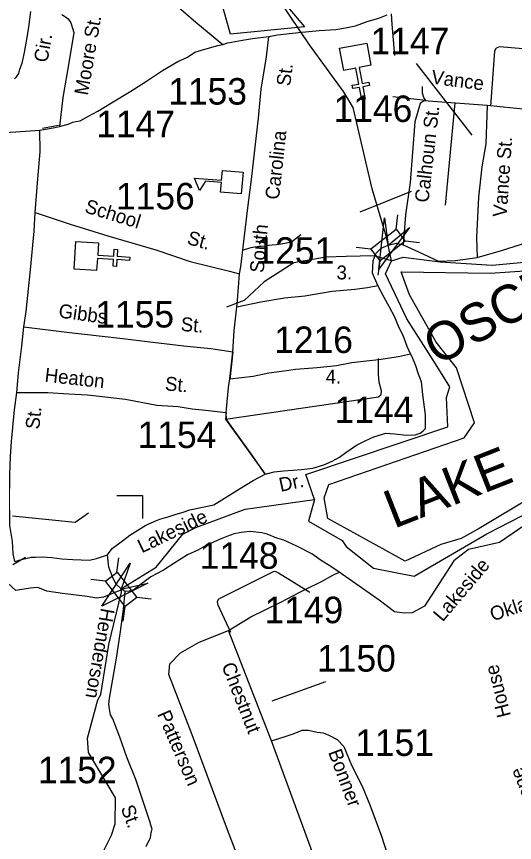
# Model space of a CAD drawing. Extents: x 884530 to 1028605, y 526725 to 653634.
# Drawn here: x 960824 to 963175, y 578430 to 582326 of the extents above; entities that cross this region are included whole.
import ezdxf

# ---------------------------------------------------------------- set-up
doc = ezdxf.new("R2010")
doc.units = 0
for name, color, linetype in [('Exist Boundary Political City Limit New', 7, 'Continuous'), ('Exist Cultural Church CELL', 7, 'Continuous'), ('Exist Cultural Educational Facility Elementary CELL', 7, 'Continuous'), ('Exist Hydrographic Bay Label', 7, 'Continuous'), ('Exist Hydrographic Buffer Line', 7, 'Continuous'), ('Exist Hydrographic Creek Single Shore', 7, 'Continuous'), ('Exist Hydrographic Lake Shore Label', 7, 'Continuous'), ('Exist Hydrographic Lock CELL', 7, 'Continuous'), ('Exist Road Non-System Type 51', 7, 'Continuous'), ('Exist Road Non-System Type 51 Label', 7, 'Continuous'), ('Exist Road Secondary Structure Standard Bridge Attributed CELL', 7, 'Continuous'), ('Exist Road Secondary Structure Standard Bridge CELL', 7, 'Continuous'), ('Exist Road Secondary Type 41 Attributed', 7, 'Continuous'), ('Exist Road Secondary Type 51 Attributed', 7, 'Continuous'), ('Exist Road Secondary Type 51 Label', 7, 'Continuous'), ('Exist Road Secondary Type 51 Number Label', 7, 'Continuous'), ('Map Preparation Boundary City Limit Buffer Line', 7, 'Continuous')]:
    doc.layers.add(name, color=color, linetype=linetype)

msp = doc.modelspace()

# ---------------------------------------------------------------- linework, layer by layer
at = {"layer": 'Exist Boundary Political City Limit New'}
msp.add_lwpolyline([(962419.1, 584388.8), (962396.4, 584268.4), (962220.6, 582634.1), (962071.3, 582412.4), (962183.8, 582276.6), (961834.8, 582241.7), (961673.8, 582812.8), (961548.6, 582823.6), (961361.7, 582493.9), (961067, 582544.3), (961105.4, 583066.7), (958842.8, 583349.2)], dxfattribs=at)
at = {"layer": 'Exist Cultural Church CELL'}
for points in [[(962497.7, 582095.6), (962441.8, 582085), (962455.9, 582010.1), (962487.3, 582016), (962490.2, 582000.3), (962458.8, 581994.4), (962469.9, 581935.3), (962454.1, 581932.4), (962443, 581991.5), (962411.6, 581985.6), (962408.6, 582001.3), (962440.1, 582007.2), (962426.1, 582082), (962369.4, 582071.5), (962349.7, 582176.1), (962478.1, 582200.2)], [(961211.1, 581257.6), (961207.6, 581200.8), (961283.6, 581195.9), (961285.7, 581227.8), (961301.6, 581226.8), (961299.6, 581194.9), (961359.6, 581191), (961358.5, 581175.1), (961298.5, 581178.9), (961296.5, 581147), (961280.5, 581148), (961282.6, 581179.9), (961206.6, 581184.8), (961202.8, 581127.3), (961096.6, 581134), (961104.9, 581264.4)]]:
    msp.add_lwpolyline(points, close=True, dxfattribs=at)
at = {"layer": 'Exist Cultural Educational Facility Elementary CELL'}
msp.add_lwpolyline([(961885.4, 581489.5), (961787.8, 581497.7), (961791.6, 581543.5), (961716.8, 581549.8), (961688.8, 581504.9), (961664.4, 581563.8), (961792.4, 581553.1), (961796.3, 581599), (961893.8, 581590.8)], close=True, dxfattribs=at)
at = {"layer": 'Exist Hydrographic Bay Label'}
for points in [[(962231.2, 580047.9), (962203.2, 579944.6), (962362.3, 579854.1), (962381, 579826), (962508.9, 579723), (962702.2, 579685.5), (963045.3, 579885.3), (963322.8, 580028.9), (963350.9, 580088.2), (963372.7, 580225.5), (963291.6, 580509.5), (963332.2, 580678.1), (963428.9, 580809.2), (963717.4, 581064.9), (963844.4, 581118.1), (963890.4, 581296.1), (963856.1, 581392.8)], [(962231.2, 580047.9), (962190.7, 580166.2), (962861.3, 580390.9), (962855, 580528.3), (962870.6, 580578.2), (962802, 580687.4), (962666.4, 580899.5), (962566.6, 581111.7), (962595.4, 581173), (962650.1, 581191.3), (962823.8, 581168.1)]]:
    msp.add_lwpolyline(points, dxfattribs=at)
at = {"layer": 'Exist Hydrographic Buffer Line'}
msp.add_lwpolyline([(963263.6, 580063.2), (963007.8, 579910.2), (962923.6, 579863.4), (962827, 579835.3), (962658.6, 579757.3), (962293.7, 579957.1), (962276.6, 580055.6), (962299.2, 580117.5), (962937.2, 580338), (962985.7, 580409.9), (962901.8, 580668.7), (962805.1, 580790.4), (962680.3, 581012.9), (962639.7, 581122.1), (963060.7, 581114.5), (963224.2, 581126.9)], dxfattribs=at)
at = {"layer": 'Exist Hydrographic Creek Single Shore'}
for points in [[(962595.4, 581173), (962571.5, 581284.8), (962503.2, 581512.8), (962414.3, 581897.2), (962368.7, 581972.4), (962207.5, 582192.9), (961744.5, 582879.2), (961617, 582987.1), (961505.9, 583064.7), (961336.7, 583108.1), (960713.9, 583186.3), (960566.8, 583274.5), (960148.7, 583287.6), (959704.9, 583646.6), (959288.3, 583677.7), (959032.2, 583745.2), (958893.2, 583826.8), (958593.5, 584078.9), (958148.8, 584242.1), (957369.3, 584369.4), (957205.1, 584441.6)], [(961320.5, 579627.6), (961311.7, 579618.6), (961235.3, 579586.3), (961201.6, 579581.8), (961157.8, 579589.6), (961042.1, 579604.3), (960967.9, 579615.5), (960925.2, 579632.4), (960888.2, 579629), (960821.3, 579618.6), (960598.8, 579821), (960504.4, 579915.4), (960482.1, 580094.7), (960172.1, 580740.4), (960009.5, 581126.8), (959664, 581416.7), (959491.2, 581482.7), (959310.4, 581426), (958932.1, 581217.6)], [(962595.4, 581173), (962513, 581196.1), (962380.1, 581193.6), (962284.4, 581191.3), (962134, 581163.9), (961992.8, 581075), (961899.3, 580986.1), (961815, 580954.1)], [(961320.5, 579627.6), (961484.5, 579728.3), (961609.5, 579884), (961670.2, 579915.4), (961904.4, 580002), (962231.2, 580047.9)], [(961152.8, 578225.7), (961272.9, 578464.9), (961289.8, 578518), (961291.4, 578639.5), (961164, 578853.7), (961159.5, 578921.2), (961208.9, 579102.2), (961222.4, 579126.9), (961260.6, 579364.1), (961320.4, 579611.1), (961320.5, 579627.6)]]:
    msp.add_lwpolyline(points, dxfattribs=at)
at = {"layer": 'Exist Hydrographic Lock CELL'}
msp.add_lwpolyline([(962823.8, 581168.1), (963070.1, 581153.4), (963220.6, 581166.8), (963388.3, 581352.3), (963494.4, 581461.5), (963640.9, 581545.8), (963821.8, 581505.2), (963856.1, 581392.8)], dxfattribs=at)
at = {"layer": 'Exist Road Non-System Type 51'}
for p, q in [((962756.6, 581929.3), (962601.5, 581946.4)), ((962893.8, 581918.9), (962847.8, 581435.5)), ((961023.3, 581810.9), (960947, 581798)), ((961845, 580744.5), (961831.7, 580613.2)), ((961814.3, 580457.1), (961810.6, 580426.7)), ((961810.6, 580426.7), (961998.4, 580166.7))]:
    msp.add_line(p, q, dxfattribs=at)
for points in [[(962593.1, 582338.2), (962596.4, 582290.2), (962608.3, 582141.3)], [(963271.8, 582168.7), (963103.9, 582183), (963089.1, 582175.8), (963080.9, 582162), (963062.6, 581903.5)], [(962756.6, 581929.3), (962747.2, 581943.7), (962741.6, 581964.7), (962740.8, 581996)], [(961895.3, 581225.7), (961921.3, 581233.3), (961932.6, 581236.1), (961947.3, 581238.8), (961959.6, 581240.6), (961969.1, 581241.8), (961978.8, 581242.8), (961996.2, 581244.7), (962013.6, 581246.6), (962030.7, 581248.4), (962052, 581250.6), (962073.9, 581253.5), (962099.2, 581258), (962111.6, 581260.6), (962122.1, 581262.9), (962166.4, 581297.4)], [(961810.6, 580426.7), (962532.7, 580531.1), (962545.7, 580542.2), (962548.2, 580560.1), (962536.7, 580601.3), (962533.8, 580637.4), (962532.7, 580668.4), (962533.8, 580712.6)], [(960805.6, 579970.5), (961100.7, 579940.7), (961165, 579984.5)], [(962209.6, 579609.4), (962061.1, 579699.5), (962050.7, 579705.8), (962043.6, 579708.6), (962036.5, 579706.3), (961803.7, 579590.1), (961786.7, 579582.2), (961775.7, 579576.1), (961772.4, 579563.5), (961775.2, 579550.7), (961834, 579421.9)]]:
    msp.add_lwpolyline(points, dxfattribs=at)
at = {"layer": 'Exist Road Secondary Structure Standard Bridge Attributed CELL'}
for points in [[(962679.5, 581330.7), (962535, 581134.2), (962562, 581376.6), (962579.4, 581247.8)], [(961445.1, 579653.1), (961227, 579543.9), (961361.2, 579747.5), (961318.2, 579624.8)]]:
    msp.add_lwpolyline(points, close=True, dxfattribs=at)
at = {"layer": 'Exist Road Secondary Structure Standard Bridge CELL'}
for p, q in [((962616.3, 581322), (962624.7, 581390.4)), ((962658.7, 581267.6), (962727.2, 581259.2)), ((962428.5, 581237.6), (962497, 581229.2)), ((962532, 581105.1), (962540.4, 581173.6)), ((960806.7, 579741.4), (960866.4, 579775.9)), ((961298.4, 579704.2), (961306.8, 579772.6)), ((961244, 579661.7), (961175.6, 579670.1)), ((961460.9, 579577.5), (961392.4, 579585.9)), ((961328.4, 579473.9), (961336.8, 579542.4))]:
    msp.add_line(p, q, dxfattribs=at)
for points in [[(962497, 581229.2), (962616.1, 581322.2), (962659.5, 581266.6), (962540.4, 581173.6)], [(961336.8, 579542.4), (961243.8, 579661.5), (961299.4, 579704.9), (961392.4, 579585.9)]]:
    msp.add_lwpolyline(points, close=True, dxfattribs=at)
at = {"layer": 'Exist Road Secondary Type 41 Attributed'}
for points in [[(960814.2, 582032.2), (960824.6, 582042), (960835.1, 582057.6), (960839.7, 582077.5), (960850.6, 582105.1), (960862.5, 582156.7), (960874.9, 582226.2), (960882.8, 582274.8), (960891.5, 582348.7)], [(961038.8, 582334.6), (961056.4, 582323.9), (961068.1, 582314.1), (961081.3, 582295.6), (961088.4, 582270), (961095.8, 582250.6), (961073.1, 582117.4), (961043.2, 581944.4), (961026.7, 581807.6)], [(961436.3, 578410.8), (961447.1, 578434.6), (961456.9, 578452), (961460, 578477.2), (961465.5, 578492.2), (961456.9, 578516.7), (961457.1, 578519.3), (961388.2, 578726.1), (961345.7, 578831.6), (961313, 578926.9), (961279.9, 579012.2), (961268.7, 579032.4), (961263.7, 579060.7), (961260.3, 579082.8), (961263.3, 579110.7), (961278.5, 579200.2), (961295.9, 579299.7), (961313.8, 579413.2), (961329.9, 579528.7), (961337.2, 579613.4)], [(962028.1, 578909.6), (962092.4, 578928.9), (962134.9, 578943.5), (962173.7, 578959.9), (962202.8, 578959.9), (962243.4, 578950.1), (962271.4, 578947.2), (962299.5, 578936.3), (962338.9, 578914.9), (962369.9, 578883.1), (962405.7, 578794), (962455.9, 578694.6), (962492.8, 578607.7), (962547.1, 578459.8), (962584.6, 578342.2), (962634.5, 578226.3), (962651.4, 578168.5), (962707.9, 578044.6)]]:
    msp.add_lwpolyline(points, dxfattribs=at)
at = {"layer": 'Exist Road Secondary Type 51 Attributed'}
for points in [[(960315.1, 582621.7), (960408.2, 582621.7), (960459.9, 582621.7), (960524.6, 582701.9), (960633.3, 582808.1), (960744.5, 582854.7), (960850.6, 582885.8), (960910.1, 582878), (960948.9, 582836.6), (960933.4, 582660.5), (960933.4, 582582.9), (960990.3, 582541.4), (961143, 582510.4), (961305.9, 582489.7), (961448.2, 582456), (961554.3, 582399), (961670.6, 582298.5), (961798.1, 582194.4)], [(962015, 582230.7), (962056.8, 582239.1), (962156, 582251.1), (962253.5, 582259.6), (962331.4, 582265.2), (962377.8, 582271.7), (962424.6, 582281.9), (962484.5, 582304.1), (962534.1, 582317.8), (962573.4, 582333.2)], [(961798.1, 582194.4), (961822.4, 582201.5), (961890.8, 582213.4), (961939.1, 582221.8), (962015, 582230.7)], [(961877.1, 581112.4), (961882.9, 581144.5), (961897, 581264.1), (961914.8, 581410.3), (961933.6, 581557.5), (961947.9, 581681.1), (961959.3, 581778.6), (961966.1, 581847), (961979.8, 581982.3), (962004.8, 582134.8), (962015, 582230.7)], [(961026.7, 581807.6), (961068.5, 581817.7), (961089.7, 581826.8), (961104.2, 581829.8), (961124.6, 581833.9), (961161.2, 581854.2), (961207.8, 581880), (961272.5, 581918.9), (961364.4, 581973.3), (961433.9, 582017), (961513.9, 582071.3), (961585.6, 582112.9), (961632.1, 582134.6), (961666.9, 582157.5), (961712.9, 582172.3), (961774.1, 582189.8), (961798.1, 582194.4)], [(963045.5, 581906.3), (962746.7, 581928.5), (962729.4, 581916.1), (962704.7, 581829.7), (962682.5, 581543), (962660.3, 581389.8), (962650.4, 581249)], [(963045.5, 581906.3), (963040.6, 581725.9), (963020.8, 581617.2), (963006, 581473.8), (962996.1, 581283.6), (962998.6, 581189.7)], [(963292.4, 581881.6), (963045.5, 581906.3)], [(960933.8, 581790.3), (960997.5, 581801), (961026.7, 581807.6)], [(960070.3, 581765.7), (960158.2, 581772.8), (960215.1, 581775.4), (960305.6, 581775.4), (960509.8, 581766.4), (960636, 581770.5), (960821.3, 581781.9), (960933.8, 581790.3)], [(960913.3, 581401.5), (960924.8, 581559.3), (960936.1, 581686.7), (960933.8, 581790.3)], [(960859.6, 580861.2), (960869.7, 580934.8), (960890.5, 581130.3), (960908, 581313.9), (960913.3, 581401.5)], [(960913.3, 581401.5), (961078.3, 581346), (961255.1, 581290.6), (961482, 581225.4), (961644.5, 581170.6), (961829.2, 581124.4), (961877.1, 581112.4)], [(963878.3, 581401.5), (963938.3, 581285.2), (963900.9, 581203.2), (963845.3, 581104.4), (963728, 581036.5), (963542.8, 580919.1), (963413.2, 580727.6), (963252.7, 580548.4), (963314.4, 580350.8), (963400.8, 580202.5), (963376.1, 580122.2), (963283.5, 579967.8), (963104.5, 579844.2), (962958.1, 579811.5), (962888.4, 579757.7), (962751.2, 579545), (962691.8, 579512.4), (962653.8, 579510.6), (962609.4, 579518.2), (962536.6, 579572.4), (962348.1, 579704.1)], [(962998.6, 581189.7), (963114.6, 581221.8), (963208.5, 581251.4), (963290, 581295.9), (963336.9, 581342.9), (963373.9, 581399.7)], [(962579.4, 581247.9), (962616.9, 581256.2), (962650.4, 581249)], [(962530.7, 581056.9), (962505, 581114.7), (962507.5, 581173.7), (962521.4, 581208), (962545.1, 581232.8), (962579.4, 581247.9)], [(962650.4, 581249), (962741.8, 581207), (962815.8, 581172.4), (962897.3, 581174.8), (962998.6, 581189.7)], [(961865.3, 580955.7), (961868.3, 580985.6), (961877.1, 581112.4)], [(961865.3, 580955.7), (961978.5, 580979.3), (962089.3, 580999.4), (962185.3, 581008.1), (962314.2, 581029.7), (962421.6, 581039.1), (962482, 581047), (962530.7, 581056.9)], [(962684.7, 580735.1), (962669.3, 580769.3), (962649.7, 580820.3), (962631.6, 580856.6), (962608.6, 580911.2), (962585.6, 580954.2), (962559.3, 581001.1), (962530.7, 581056.9)], [(961845, 580744.5), (961852.5, 580843.1), (961865.3, 580955.7)], [(960826.2, 580552.9), (960834.5, 580645.7), (960849.1, 580770.7), (960859.6, 580861.2)], [(960859.6, 580861.2), (961074.5, 580835.9), (961146.1, 580827.7), (961327, 580806.6), (961453.2, 580791.8), (961629.1, 580771), (961741.8, 580759.7), (961845, 580744.5)], [(961831, 580616.9), (961845, 580744.5)], [(961831, 580616.9), (961942.2, 580628.9), (962016.1, 580644.8), (962098.3, 580655.9), (962141.8, 580662.1), (962244.2, 580670.4), (962335.7, 580680.3), (962408, 580693), (962476.4, 580700.8), (962534.1, 580707.7), (962628.2, 580721.4), (962684.7, 580735.1)], [(961998.4, 580166.7), (962040.5, 580178.7), (962084.4, 580182.4), (962130.1, 580185.9), (962170.5, 580188.8), (962222.8, 580195), (962274.5, 580211.3), (962314.8, 580228.5), (962349.2, 580247.7), (962378.9, 580269.8), (962429.7, 580303.3), (962470.9, 580324.4), (962511.2, 580342.6), (962567.7, 580359.9), (962608.9, 580357), (962666.4, 580350.3), (962707.1, 580352.4), (962729.4, 580360.9), (962744.8, 580371.2), (962753.3, 580381.5), (962754.5, 580386.1), (962755.5, 580403), (962755.5, 580419.3), (962755.5, 580447.1), (962742.5, 580543), (962736, 580603.2), (962722.3, 580639.2), (962709.7, 580677.3), (962692.9, 580719.9), (962684.7, 580735.1)], [(961814.3, 580457.1), (961815.8, 580473.9), (961825.3, 580576.4), (961831, 580616.9)], [(960816.3, 579754.4), (960809.1, 579793.2), (960805, 579849.3), (960793.2, 579925.6), (960792.6, 579967.6), (960790.9, 580029.7), (960793.6, 580165.7), (960795.9, 580250.9), (960800.3, 580320.8), (960814.9, 580470.4), (960826.2, 580552.9)], [(960826.2, 580552.9), (960973, 580551.8), (961070.9, 580546.4), (961158.8, 580541.2), (961338.3, 580521), (961487.3, 580492.7), (961588.3, 580485.9), (961653.3, 580475.6), (961716.6, 580468.8), (961814.3, 580457.1)], [(961998.4, 580166.7), (961940.4, 580251.6), (961882.9, 580329.9), (961815.8, 580425.6), (961814.3, 580457.1)], [(961254.3, 579787.2), (961275.9, 579816.1), (961325.5, 579852.1), (961359.8, 579879.5), (961435, 579926.7), (961485.9, 579949.1), (961501.7, 579954.8), (961545.5, 579967.2), (961572.9, 579977.4), (961610.5, 579987.7), (961643, 579998), (961755.9, 580022), (961877.6, 580098.2), (961942.3, 580137), (961998.4, 580166.7)], [(962348.1, 579704.1), (962308, 579732), (962262.7, 579759.9), (962218.3, 579791), (962147.4, 579827.5), (962086.5, 579856.4), (962052.9, 579865.5), (962008.4, 579883.7), (961982.2, 579890.7), (961928.2, 579895.9), (961884.7, 579892.4), (961851.6, 579885.4), (961816.9, 579872.7), (961794.5, 579863.5), (961757.5, 579847.1), (961713.2, 579827.9), (961680.6, 579808.9), (961631, 579786.5), (961571.6, 579748.5), (961518.3, 579714.4), (961459.2, 579682.3), (961415.1, 579649.7), (961378.3, 579621.6), (961355.9, 579614.4), (961337.2, 579613.4)], [(960816.3, 579754.4), (960853.4, 579766.5), (960868.6, 579768.5), (960893, 579775.8), (960912.2, 579775), (960948.3, 579777.7), (960991.2, 579773.6), (961038.8, 579767.8), (961090.3, 579763.7), (961168.3, 579761), (961201.4, 579768.7), (961254.3, 579787.2)], [(961317.8, 579626), (961294.6, 579648.4), (961279.6, 579678.5), (961260.4, 579727.6), (961254.3, 579787.2)], [(961824.4, 579429.8), (961931, 579494), (962071.6, 579563), (962161.2, 579610), (962189.7, 579625), (962267, 579662.3), (962318, 579690.7), (962348.1, 579704.1)], [(961337.2, 579613.4), (961317.8, 579626)], [(962144.7, 577656.5), (962053.8, 577881.1), (961820.8, 578489.6), (961653.2, 578937.8), (961544, 579222.1), (961547.6, 579273.1), (961598.6, 579324.1), (961686, 579375.1), (961824.4, 579429.8)], [(962028.1, 578909.6), (961824.4, 579429.8)], [(962416.8, 577864.1), (962232.1, 578352), (962028.1, 578909.6)]]:
    msp.add_lwpolyline(points, dxfattribs=at)
at = {"layer": 'Exist Road Secondary Type 51 Label'}
for points in [[(962446.3, 581404.7), (962688.5, 581502.6)], [(961298.2, 580065.8), (961418.9, 580065.8), (961418.9, 579958.3)], [(962283.8, 579188.1), (962029.6, 579095.9)]]:
    msp.add_lwpolyline(points, dxfattribs=at)
at = {"layer": 'Exist Road Secondary Type 51 Number Label'}
msp.add_lwpolyline([(962976, 581765.9), (962712.3, 582104.2)], dxfattribs=at)
at = {"layer": 'Map Preparation Boundary City Limit Buffer Line'}
msp.add_lwpolyline([(962419.1, 584388.8), (962396.4, 584268.4), (962220.6, 582634.1), (962071.3, 582412.4), (962183.8, 582276.6), (961834.8, 582241.7), (961673.8, 582812.8), (961548.6, 582823.6), (961361.7, 582493.9), (961067, 582544.3), (961105.4, 583066.7), (958842.8, 583349.2)], dxfattribs=at)

# ---------------------------------------------------------------- texts
at = {"layer": 'Exist Hydrographic Lake Shore Label'}
for s, rotation, p in [('OSCEOLA', 29.4472, (962812.6, 580675.3)), ('OSCEOLA', 29.4472, (962812.6, 580675.3)), ('LAKE', 21.458, (962605.6, 579908.5)), ('LAKE', 21.458, (962605.6, 579908.5))]:
    msp.add_text(s, height=180.45, rotation=rotation, dxfattribs=at).set_placement(p)
at = {"layer": 'Exist Road Non-System Type 51 Label'}
msp.add_text('Oklahoma St.', height=65.617, rotation=17.8618, dxfattribs=at).set_placement((963071.7, 579472.8))
at = {"layer": 'Exist Road Secondary Type 51 Label'}
for s, height, rotation, p in [('Moore St.', 65.62, 80.3335, (961161.2, 581950.9)), ('Cir.', 65.62, 79.8913, (960970, 582105.8)), ('St.', 65.62, 83.1296, (962116.3, 581994.7)), ('Vance', 65.62, 352.4697, (962779.8, 582009.4)), ('Calhoun St.', 65.617, 83.4664, (962768.9, 581445.5)), ('Carolina', 65.62, 83.6979, (962063.2, 581459.5)), ('Vance St.', 65.62, 85.9798, (963137.9, 581378)), ('School', 65.62, 342.9517, (961142.2, 581403)), ('South', 65.62, 84.7899, (961990.8, 581114.5)), ('St.', 65.62, 343.8883, (961625.4, 581253.9)), ('Gibbs', 65.62, 352.1595, (961020.1, 580906.6)), ('St.', 65.62, 355.0522, (961597.8, 580843.1)), ('Heaton', 65.62, 353.5716, (960955.1, 580603.6)), ('St.', 65.62, 354.9266, (961523.4, 580562.6)), ('St.', 65.62, 84.2521, (960931.7, 580376.2)), ('Dr.', 65.62, 12.208, (962071.3, 580083.4)), ('Lakeside', 65.62, 25.6094, (961415.8, 579793.1)), ('Lakeside', 65.62, 49.7406, (962835.8, 579467.2)), ('Henderson', 65.62, 260.0751, (961223.6, 579538.4)), ('Chestnut', 65.62, 291.5488, (961791, 579264)), ('House', 65.62, 104.1969, (963158.8, 579028.4)), ('Patterson', 65.62, 293.2739, (961487.3, 579035.8)), ('Bonner', 65.62, 290.627, (962294.7, 578855.6)), ('Stone', 65.62, 111.3417, (963293.9, 578576.4)), ('St.', 65.62, 290.4204, (961315.5, 578592.6))]:
    msp.add_text(s, height=height, rotation=rotation, dxfattribs=at).set_placement(p)
for s, p in [('3.', (962335.2, 581085.6)), ('4.', (962284, 580594.5))]:
    msp.add_text(s, height=65.62, dxfattribs=at).set_placement(p)
at = {"layer": 'Exist Road Secondary Type 51 Number Label'}
for s, p in [('1147', (962495.6, 582147.8)), ('1153', (961540.6, 581910.3)), ('1146', (962321, 581828.2)), ('1147', (961200.6, 581756.6)), ('1156', (961294, 581416)), ('1251', (961952.7, 581159.4)), ('1155', (961196.4, 580858.8)), ('1216', (962040.7, 580738.5)), ('1144', (962325.7, 580408.3)), ('1154', (961396.1, 580290.4)), ('1148', (961689.4, 579720.7)), ('1149', (961995, 579464)), ('1150', (962243.4, 579235.7)), ('1151', (962423.1, 578838)), ('1152', (960925.3, 578709.1))]:
    msp.add_text(s, height=125, dxfattribs=at).set_placement(p)

doc.saveas('drawing.dxf')
